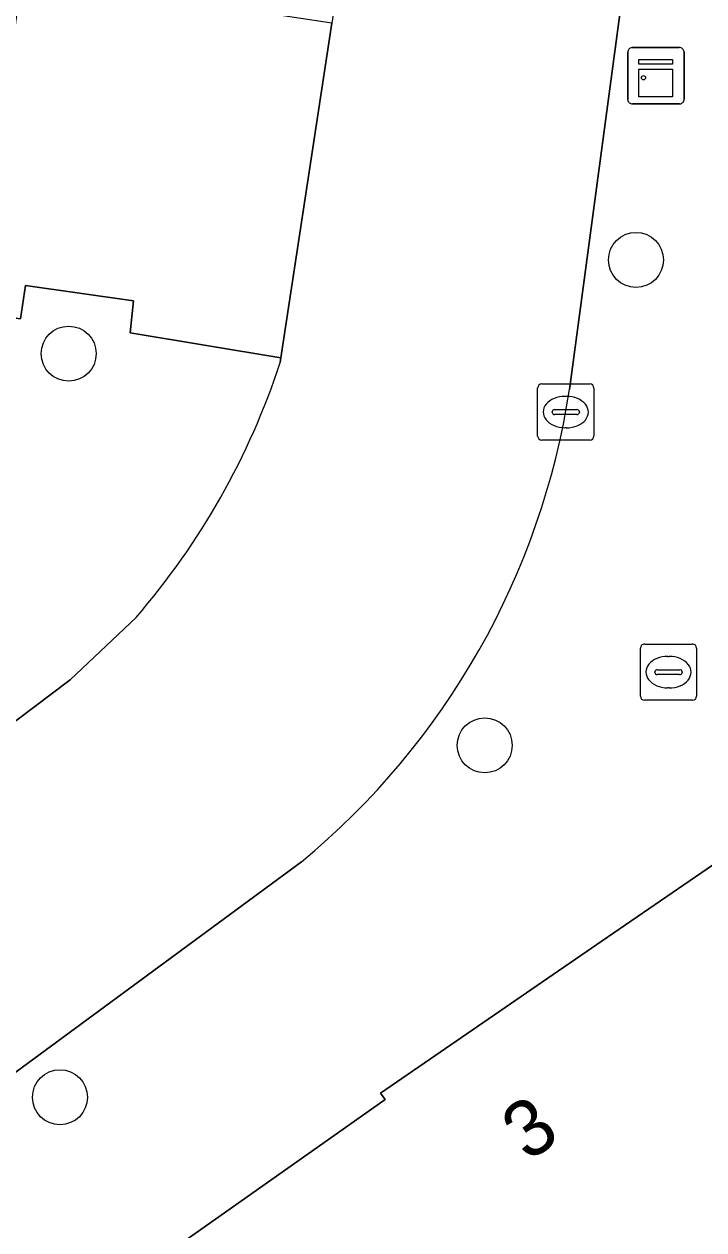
# Model space of a CAD drawing. Extents: x 160663 to 161506, y 382245 to 383291.
# Drawn here: x 160901.63 to 160913.72, y 383220.36 to 383241.8 of the extents above; entities that cross this region are included whole.
import ezdxf

# ---------------------------------------------------------------- set-up
doc = ezdxf.new("R2010")
doc.units = 0
for name, color, linetype in [('IMGEO_Boom', 7, 'Continuous'), ('IMGEO_Kast', 7, 'Continuous'), ('IMGEO_Kolk', 7, 'Continuous'), ('IMGEO_Pand', 7, 'Continuous'), ('IMGEO_Pand_nummerreeks', 7, 'Continuous'), ('IMGEO_Rijbaan_lokaal_gesloten', 7, 'Continuous'), ('IMGEO_Rijbaan_lokaal_open', 7, 'Continuous'), ('IMGEO_Rioolput', 7, 'Continuous'), ('IMGEO_Voetpad_gesloten', 7, 'Continuous'), ('IMGEO_Voetpad_open', 7, 'Continuous')]:
    doc.layers.add(name, color=color, linetype=linetype)

msp = doc.modelspace()

# ---------------------------------------------------------------- linework, layer by layer
at = {"layer": 'IMGEO_Boom'}
for centre in [(160912.513, 383237.607), (160902.424, 383235.941), (160909.823, 383228.976), (160902.269, 383222.719)]:
    msp.add_circle(centre, 0.489, dxfattribs=at)
at = {"layer": 'IMGEO_Kast'}
for p, q in [((160912.443, 383241.382), (160913.284, 383241.382)), ((160913.284, 383241.382), (160912.443, 383241.382)), ((160913.368, 383241.307), (160913.368, 383240.466)), ((160913.368, 383240.466), (160913.368, 383241.307)), ((160912.368, 383240.457), (160912.368, 383241.298)), ((160912.368, 383241.298), (160912.368, 383240.457)), ((160913.293, 383240.382), (160912.452, 383240.382)), ((160912.452, 383240.382), (160913.293, 383240.382))]:
    msp.add_line(p, q, dxfattribs=at)
for points in [[(160912.563, 383241.172), (160913.163, 383241.172), (160913.163, 383241.087), (160912.563, 383241.087), (160912.563, 383241.172)], [(160912.563, 383240.997), (160913.163, 383240.997), (160913.163, 383240.508), (160912.563, 383240.508), (160912.563, 383240.997)]]:
    msp.add_lwpolyline(points, dxfattribs=at)
msp.add_circle((160912.647, 383240.846), 0.0377, dxfattribs=at)
for centre, start, end in [((160912.446, 383241.304), 92.4484, 184.2845), ((160912.446, 383241.304), 92.4484, 184.2845), ((160913.29, 383241.304), 2.4484, 94.2845), ((160913.29, 383241.304), 2.4484, 94.2845), ((160912.446, 383240.46), 182.4484, 274.2845), ((160912.446, 383240.46), 182.4484, 274.2845), ((160913.29, 383240.46), 272.4484, 4.2845), ((160913.29, 383240.46), 272.4484, 4.2845)]:
    msp.add_arc(centre, 0.0779, start, end, dxfattribs=at)
at = {"layer": 'IMGEO_Kolk'}
for p, q in [((160910.764, 383234.476), (160910.764, 383235.328)), ((160910.839, 383235.402), (160911.691, 383235.402)), ((160911.765, 383235.328), (160911.765, 383234.476)), ((160911.252, 383235.182), (160911.277, 383235.182)), ((160911.023, 383234.896), (160911.023, 383234.908)), ((160911.066, 383234.945), (160911.464, 383234.945)), ((160911.507, 383234.908), (160911.507, 383234.896)), ((160911.461, 383234.859), (160911.063, 383234.859)), ((160911.275, 383234.622), (160911.25, 383234.622)), ((160911.691, 383234.402), (160910.839, 383234.402))]:
    msp.add_line(p, q, dxfattribs=at)
for points in [[(160910.764, 383234.476), (160910.764, 383235.328)], [(160910.839, 383235.402), (160911.691, 383235.402)], [(160911.765, 383235.328), (160911.765, 383234.476)], [(160911.691, 383234.402), (160910.839, 383234.402)]]:
    msp.add_lwpolyline(points, dxfattribs=at)
for centre, radius, start, end in [((160910.841, 383235.326), 0.0765, 91.552, 178.448), ((160910.841, 383235.326), 0.0765, 91.552, 178.448), ((160911.689, 383235.326), 0.0765, 1.552, 88.448), ((160911.689, 383235.326), 0.0765, 1.552, 88.448), ((160911.063, 383234.905), 0.0403, 85.8775, 175.7526), ((160911.06, 383234.895), 0.0366, 178.938, 274.7102), ((160911.464, 383234.902), 0.043, 264.8664, 352.4533), ((160911.468, 383234.907), 0.0386, 1.7309, 96.639), ((160910.841, 383234.478), 0.0765, 181.552, 268.448), ((160910.841, 383234.478), 0.0765, 181.552, 268.448), ((160911.689, 383234.478), 0.0765, 271.552, 358.448), ((160911.689, 383234.478), 0.0765, 271.552, 358.448)]:
    msp.add_arc(centre, radius, start, end, dxfattribs=at)
for centre, major_axis, ratio, start_param, end_param in [((160911.251, 383234.902), (-0.387, 0.002), 0.722429, 4.712389, 7.853982), ((160911.276, 383234.902), (-0.39, 0.002), 0.717154, 1.570796, 4.712389)]:
    msp.add_ellipse(centre, major_axis=major_axis, ratio=ratio, start_param=start_param, end_param=end_param, dxfattribs=at)
at = {"layer": 'IMGEO_Pand'}
msp.add_lwpolyline([(160934.839, 383215.352), (160924.877, 383216.69), (160923.861, 383218.164), (160921.453, 383221.578), (160916.477, 383228.632), (160911.914, 383225.501), (160907.969, 383222.794), (160908.052, 383222.677), (160907.507, 383222.293), (160903.028, 383219.134), (160912.302, 383205.933), (160914.684, 383207.522), (160916.579, 383204.9), (160917.513, 383205.67), (160917.929, 383205.614), (160920.444, 383205.276), (160922.404, 383205.013), (160930.064, 383203.984), (160936.842, 383210.957), (160934.567, 383213.466)], close=True, dxfattribs=at)
at = {"layer": 'IMGEO_Rijbaan_lokaal_gesloten'}
for points in [[(160912.522, 383244.195), (160912.882, 383247.022), (160913.396, 383250.103), (160908.598, 383250.707), (160907.598, 383245.026), (160907.107, 383241.817), (160906.197, 383235.866), (160906.184, 383235.781)], [(160911.331, 383235.302), (160912.522, 383244.195)], [(160903.622, 383231.251), (160902.449, 383230.144), (160897.372, 383226.313), (160897.375, 383226.308), (160900.314, 383222.312), (160906.564, 383226.907)]]:
    msp.add_lwpolyline(points, dxfattribs=at)
for centre, radius, start, end in [((160893.648, 383239.882), 13.19, 319.1309, 341.8873), ((160897.947, 383237.351), 13.54, 309.5251, 351.2958)]:
    msp.add_arc(centre, radius, start, end, dxfattribs=at)
at = {"layer": 'IMGEO_Rijbaan_lokaal_open'}
msp.add_lwpolyline([(160907.107, 383241.817), (160901.594, 383242.653), (160901.483, 383241.871), (160900.782, 383236.68), (160901.569, 383236.562), (160901.654, 383237.155), (160903.574, 383236.879), (160903.519, 383236.311), (160906.197, 383235.866)], close=True, dxfattribs=at)
at = {"layer": 'IMGEO_Rioolput'}
for p, q in [((160912.591, 383229.852), (160912.591, 383230.704)), ((160912.666, 383230.778), (160913.518, 383230.778)), ((160913.592, 383230.704), (160913.592, 383229.852)), ((160913.079, 383230.558), (160913.104, 383230.558)), ((160912.85, 383230.272), (160912.85, 383230.284)), ((160913.288, 383230.235), (160912.89, 383230.235)), ((160912.893, 383230.321), (160913.291, 383230.321)), ((160913.334, 383230.284), (160913.334, 383230.272)), ((160913.102, 383229.998), (160913.077, 383229.998)), ((160913.518, 383229.778), (160912.666, 383229.778))]:
    msp.add_line(p, q, dxfattribs=at)
for points in [[(160912.591, 383229.852), (160912.591, 383230.704)], [(160912.666, 383230.778), (160913.518, 383230.778)], [(160913.592, 383230.704), (160913.592, 383229.852)], [(160913.518, 383229.778), (160912.666, 383229.778)]]:
    msp.add_lwpolyline(points, dxfattribs=at)
for centre, radius, start, end in [((160912.668, 383230.702), 0.0765, 91.552, 178.448), ((160912.668, 383230.702), 0.0765, 91.552, 178.448), ((160913.516, 383230.702), 0.0765, 1.552, 88.448), ((160913.516, 383230.702), 0.0765, 1.552, 88.448), ((160912.89, 383230.281), 0.0403, 85.8775, 175.7526), ((160912.887, 383230.271), 0.0366, 178.938, 274.7102), ((160913.291, 383230.278), 0.043, 264.8664, 352.4533), ((160913.295, 383230.283), 0.0386, 1.7309, 96.639), ((160912.668, 383229.854), 0.0765, 181.552, 268.448), ((160912.668, 383229.854), 0.0765, 181.552, 268.448), ((160913.516, 383229.854), 0.0765, 271.552, 358.448), ((160913.516, 383229.854), 0.0765, 271.552, 358.448)]:
    msp.add_arc(centre, radius, start, end, dxfattribs=at)
for centre, major_axis, ratio, start_param, end_param in [((160913.078, 383230.278), (-0.387, 0.002), 0.722429, 4.712389, 7.853982), ((160913.103, 383230.278), (-0.39, 0.002), 0.717154, 1.570796, 4.712389)]:
    msp.add_ellipse(centre, major_axis=major_axis, ratio=ratio, start_param=start_param, end_param=end_param, dxfattribs=at)
at = {"layer": 'IMGEO_Voetpad_gesloten'}
for points in [[(160917.764, 383246.459), (160912.882, 383247.022), (160912.522, 383244.195), (160911.331, 383235.302)], [(160896.291, 383212.902), (160897.356, 383213.691), (160898.581, 383214.72), (160898.739, 383216.109), (160903.028, 383219.134), (160907.507, 383222.293), (160908.052, 383222.677), (160907.969, 383222.794), (160911.914, 383225.501), (160916.477, 383228.632), (160915.546, 383229.952), (160917.764, 383246.459)], [(160906.564, 383226.907), (160900.314, 383222.312), (160897.743, 383220.361)]]:
    msp.add_lwpolyline(points, dxfattribs=at)
msp.add_arc((160897.947, 383237.351), 13.54, 309.5251, 351.2958, dxfattribs=at)
at = {"layer": 'IMGEO_Voetpad_open'}
for points in [[(160906.184, 383235.781), (160906.197, 383235.866), (160903.519, 383236.311), (160903.574, 383236.879), (160901.654, 383237.155), (160901.569, 383236.562), (160900.782, 383236.68), (160900.757, 383236.496)], [(160897.847, 383235.797), (160897.351, 383232.331), (160897.259, 383231.684), (160899.2, 383231.413), (160899.37, 383231.41), (160899.544, 383231.406), (160899.645, 383231.34), (160896.698, 383228.981), (160895.429, 383229.121), (160894.805, 383224.42), (160897.372, 383226.313), (160902.449, 383230.144), (160903.622, 383231.251)]]:
    msp.add_lwpolyline(points, dxfattribs=at)
msp.add_arc((160893.648, 383239.882), 13.19, 319.1309, 341.8873, dxfattribs=at)

# ---------------------------------------------------------------- texts
at = {"layer": 'IMGEO_Pand_nummerreeks'}
msp.add_text('3', height=1, rotation=34.4577, dxfattribs=at).set_placement((160910.589, 383221.56))

doc.saveas('drawing.dxf')
